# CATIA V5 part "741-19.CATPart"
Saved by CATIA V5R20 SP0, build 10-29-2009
Part number: 741-19
Bounding box of the stored display mesh (mm): x -20 to 19.771, y -19.965 to 19.916, z -23 to 20
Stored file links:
  C:\Users\Utente\Desktop\IO LAVORO\3D X SITO CF\X SITO\741\741-19.CATPart
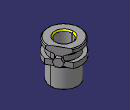
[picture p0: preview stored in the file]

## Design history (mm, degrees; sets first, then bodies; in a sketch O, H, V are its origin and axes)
Set1
  DatumSurface1 to DatumSurface44 "741-19"
Body1 (main body)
